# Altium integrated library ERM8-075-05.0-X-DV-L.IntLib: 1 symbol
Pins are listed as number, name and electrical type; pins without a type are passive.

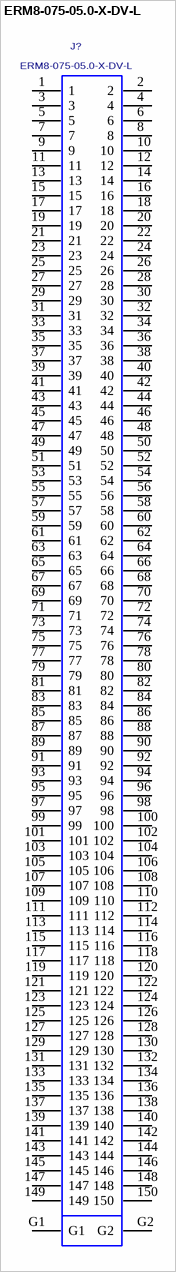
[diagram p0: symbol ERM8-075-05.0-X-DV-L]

## ERM8-075-05.0-X-DV-L
designator J?
0.8mm Edge Rate Terminal Assembly, Double Vertical Row, 75 Positions, 0.8mm Pitch; MANUFACTURER: SAMTEC
footprint ERM8-075-05.0-X-DV-L
pins: 1, 2, 3, 4, 5, 6, 7, 8, 9, 10, 11, 12, 13, 14, 15, 16, 17, 18, 19, 20, 21, 22, 23, 24, 25, 26, 27, 28, 29, 30, 31, 32, 33, 34, 35, 36, 37, 38, 39, 40, 41, 42, 43, 44, 45, 46, 47, 48, 49, 50, 51, 52, 53, 54, 55, 56, 57, 58, 59, 60, 61, 62, 63, 64, 65, 66, 67, 68, 69, 70, 71, 72, 73, 74, 75, 76, 77, 78, 79, 80, 81, 82, 83, 84, 85, 86, 87, 88, 89, 90, 91, 92, 93, 94, 95, 96, 97, 98, 99, 100, 101, 102, 103, 104, 105, 106, 107, 108, 109, 110, 111, 112, 113, 114, 115, 116, 117, 118, 119, 120, 121, 122, 123, 124, 125, 126, 127, 128, 129, 130, 131, 132, 133, 134, 135, 136, 137, 138, 139, 140, 141, 142, 143, 144, 145, 146, 147, 148, 149, 150, G1, G2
